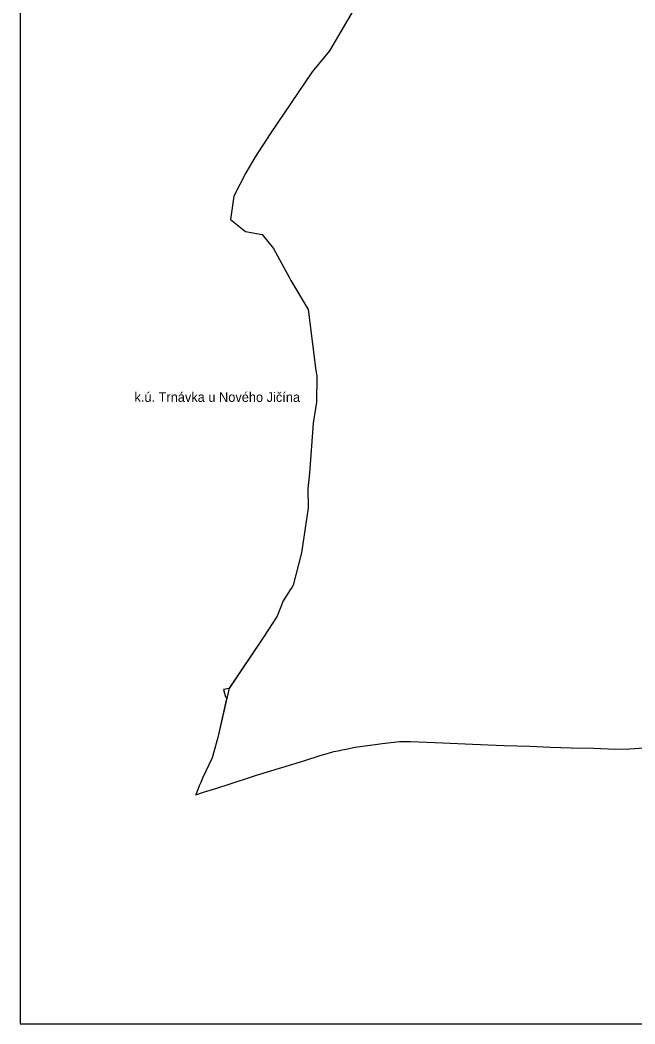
# Model space of a CAD drawing. Extents: x -478440 to -472455, y -1118045 to -1113755.
# Drawn here: x -478440 to -477154, y -1118000 to -1115899 of the extents above; entities that cross this region are included whole.
import ezdxf

# ---------------------------------------------------------------- set-up
doc = ezdxf.new("R2010")
doc.units = 0
for name, color, linetype in [('hranice kú', 7, 'Continuous'), ('Implicitní', 7, 'Continuous'), ('ObPÚ', 7, 'Continuous'), ('okolní k_ú_', 7, 'Continuous')]:
    doc.layers.add(name, color=color, linetype=linetype)

msp = doc.modelspace()

# ---------------------------------------------------------------- linework, layer by layer
at = {"layer": 'hranice kú'}
for p, q in [((-477745.7, -1115882.6), (-477792.7, -1115963.5)), ((-477792.7, -1115963.5), (-477829.2, -1116007.1)), ((-477829.2, -1116007.1), (-477917, -1116137.1)), ((-477917, -1116137.1), (-477949.4, -1116186.8)), ((-477949.4, -1116186.8), (-477967.8, -1116218.8)), ((-477967.8, -1116218.8), (-477992.9, -1116267.5)), ((-477992.9, -1116267.5), (-478000.3, -1116316.6)), ((-478000.3, -1116316.6), (-477968.7, -1116341.6)), ((-477968.7, -1116341.6), (-477933.8, -1116347.4)), ((-477933.8, -1116347.4), (-477910, -1116376.7)), ((-477910, -1116376.7), (-477876.7, -1116438.2)), ((-477876.7, -1116438.2), (-477873.6, -1116444)), ((-477873.6, -1116444), (-477837.5, -1116504.5)), ((-477837.5, -1116504.5), (-477821.5, -1116632.6)), ((-477821.5, -1116632.6), (-477819.1, -1116643.3)), ((-477819.1, -1116643.3), (-477819.9, -1116698.8)), ((-477819.9, -1116698.8), (-477826.9, -1116742.9)), ((-477826.9, -1116742.9), (-477835, -1116847.4)), ((-477835, -1116847.4), (-477838.2, -1116880.3)), ((-477838.2, -1116880.3), (-477837.4, -1116919.6)), ((-477837.4, -1116919.6), (-477851.4, -1117014.1)), ((-477851.4, -1117014.1), (-477868.8, -1117081.8)), ((-477871.9, -1117086.5), (-477874.9, -1117091.3)), ((-477868.8, -1117081.8), (-477871.9, -1117086.5)), ((-477874.9, -1117091.3), (-477889.7, -1117114.6)), ((-477889.7, -1117114.6), (-477902.7, -1117146.6)), ((-477902.7, -1117146.6), (-477931, -1117190.8)), ((-477931, -1117190.8), (-478003, -1117297.4)), ((-478003, -1117297.4), (-478026.4, -1117400.7)), ((-478026.4, -1117400.7), (-478038.6, -1117443)), ((-477766.4, -1117426.5), (-477761.5, -1117425.5)), ((-477761.5, -1117425.5), (-477739.4, -1117421.1)), ((-477739.4, -1117421.1), (-477692.8, -1117414.3)), ((-477692.8, -1117414.3), (-477683, -1117413.2)), ((-477683, -1117413.2), (-477646.5, -1117409)), ((-477646.5, -1117409), (-477622.5, -1117408.8)), ((-477622.5, -1117408.8), (-477556, -1117411.8)), ((-477556, -1117411.8), (-477494.1, -1117414.8)), ((-477494.1, -1117414.8), (-477427.6, -1117417.5)), ((-477427.6, -1117417.5), (-477374.1, -1117418.9)), ((-477374.1, -1117418.9), (-477330.4, -1117420.6)), ((-477330.4, -1117420.6), (-477287.5, -1117422.1)), ((-477287.5, -1117422.1), (-477240.8, -1117423)), ((-477240.8, -1117423), (-477193.8, -1117425.2)), ((-477193.8, -1117425.2), (-477165.8, -1117424.6)), ((-477165.8, -1117424.6), (-477134.7, -1117422.1)), ((-478038.6, -1117443), (-478058.5, -1117486)), ((-477846.5, -1117449.7), (-477810.1, -1117437.4)), ((-477810.1, -1117437.4), (-477802.8, -1117435.4)), ((-477802.8, -1117435.4), (-477797.7, -1117434)), ((-477797.7, -1117434), (-477792.8, -1117432.8)), ((-477792.8, -1117432.8), (-477783.8, -1117430)), ((-477783.8, -1117430), (-477771.4, -1117427.5)), ((-477771.4, -1117427.5), (-477766.4, -1117426.5)), ((-477945.6, -1117479.7), (-477846.5, -1117449.7)), ((-478058.5, -1117486), (-478062.4, -1117495)), ((-478009.3, -1117500.1), (-477945.6, -1117479.7)), ((-478065.9, -1117501.8), (-478072.8, -1117520.4)), ((-478062.4, -1117495), (-478065.9, -1117501.8)), ((-478049.8, -1117513.1), (-478028.9, -1117506.3)), ((-478028.9, -1117506.3), (-478024.4, -1117504.9)), ((-478024.4, -1117504.9), (-478019.9, -1117503.5)), ((-478019.9, -1117503.5), (-478009.3, -1117500.1)), ((-478072.8, -1117520.4), (-478058.8, -1117515.9)), ((-478058.8, -1117515.9), (-478054.3, -1117514.5)), ((-478054.3, -1117514.5), (-478049.8, -1117513.1))]:
    msp.add_line(p, q, dxfattribs=at)
at = {"layer": 'Implicitní'}
msp.add_lwpolyline([(-478440.1, -1118000.1), (-472500.1, -1118000.1), (-472500.1, -1113800.1), (-478440.1, -1113800.1)], close=True, dxfattribs=at)
at = {"layer": 'ObPÚ'}
for p, q in [((-477745.7, -1115882.6), (-477792.7, -1115963.5)), ((-477792.7, -1115963.5), (-477829.2, -1116007.1)), ((-477829.2, -1116007.1), (-477917, -1116137.1)), ((-477917, -1116137.1), (-477949.4, -1116186.8)), ((-477949.4, -1116186.8), (-477967.8, -1116218.8)), ((-477967.8, -1116218.8), (-477992.9, -1116267.5)), ((-477992.9, -1116267.5), (-478000.3, -1116316.6)), ((-478000.3, -1116316.6), (-477968.7, -1116341.6)), ((-477968.7, -1116341.6), (-477933.8, -1116347.4)), ((-477933.8, -1116347.4), (-477910, -1116376.7)), ((-477910, -1116376.7), (-477876.7, -1116438.2)), ((-477876.7, -1116438.2), (-477873.6, -1116444)), ((-477873.6, -1116444), (-477837.5, -1116504.5)), ((-477837.5, -1116504.5), (-477821.5, -1116632.6)), ((-477821.5, -1116632.6), (-477819.1, -1116643.3)), ((-477819.1, -1116643.3), (-477819.9, -1116698.8)), ((-477819.9, -1116698.8), (-477826.9, -1116742.9)), ((-477826.9, -1116742.9), (-477835, -1116847.4)), ((-477835, -1116847.4), (-477838.2, -1116880.3)), ((-477838.2, -1116880.3), (-477837.4, -1116919.6)), ((-477837.4, -1116919.6), (-477851.4, -1117014.1)), ((-477851.4, -1117014.1), (-477868.8, -1117081.8)), ((-477871.9, -1117086.5), (-477874.9, -1117091.3)), ((-477868.8, -1117081.8), (-477871.9, -1117086.5)), ((-477874.9, -1117091.3), (-477889.7, -1117114.6)), ((-477889.7, -1117114.6), (-477902.7, -1117146.6)), ((-477902.7, -1117146.6), (-477931, -1117190.8)), ((-478007.7, -1117316.1), (-478026.4, -1117400.7)), ((-478026.4, -1117400.7), (-478038.6, -1117443)), ((-477766.4, -1117426.5), (-477761.5, -1117425.5)), ((-477761.5, -1117425.5), (-477739.4, -1117421.1)), ((-477739.4, -1117421.1), (-477692.8, -1117414.3)), ((-477692.8, -1117414.3), (-477683, -1117413.2)), ((-477683, -1117413.2), (-477646.5, -1117409)), ((-477646.5, -1117409), (-477622.5, -1117408.8)), ((-477622.5, -1117408.8), (-477556, -1117411.8)), ((-477556, -1117411.8), (-477494.1, -1117414.8)), ((-477494.1, -1117414.8), (-477427.6, -1117417.5)), ((-477427.6, -1117417.5), (-477374.1, -1117418.9)), ((-477374.1, -1117418.9), (-477330.4, -1117420.6)), ((-477330.4, -1117420.6), (-477287.5, -1117422.1)), ((-477287.5, -1117422.1), (-477240.8, -1117423)), ((-477240.8, -1117423), (-477193.8, -1117425.2)), ((-477193.8, -1117425.2), (-477165.8, -1117424.6)), ((-477165.8, -1117424.6), (-477134.7, -1117422.1)), ((-478038.6, -1117443), (-478058.5, -1117486)), ((-477846.5, -1117449.7), (-477810.1, -1117437.4)), ((-477810.1, -1117437.4), (-477802.8, -1117435.4)), ((-477802.8, -1117435.4), (-477797.7, -1117434)), ((-477797.7, -1117434), (-477792.8, -1117432.8)), ((-477792.8, -1117432.8), (-477783.8, -1117430)), ((-477783.8, -1117430), (-477771.4, -1117427.5)), ((-477771.4, -1117427.5), (-477766.4, -1117426.5)), ((-477945.6, -1117479.7), (-477846.5, -1117449.7)), ((-478058.5, -1117486), (-478062.4, -1117495)), ((-478009.3, -1117500.1), (-477945.6, -1117479.7)), ((-478065.9, -1117501.8), (-478072.8, -1117520.4)), ((-478062.4, -1117495), (-478065.9, -1117501.8)), ((-478049.8, -1117513.1), (-478028.9, -1117506.3)), ((-478028.9, -1117506.3), (-478024.4, -1117504.9)), ((-478024.4, -1117504.9), (-478019.9, -1117503.5)), ((-478019.9, -1117503.5), (-478009.3, -1117500.1)), ((-478072.8, -1117520.4), (-478058.8, -1117515.9)), ((-478058.8, -1117515.9), (-478054.3, -1117514.5)), ((-478054.3, -1117514.5), (-478049.8, -1117513.1))]:
    msp.add_line(p, q, dxfattribs=at)
msp.add_lwpolyline([(-477931, -1117190.8), (-478003.1, -1117297.8), (-478014.9, -1117299.8), (-478010.7, -1117315.5), (-478007.7, -1117316.1)], dxfattribs=at)

# ---------------------------------------------------------------- texts
at = {"layer": 'okolní k_ú_'}
msp.add_text('k.ú. Trnávka u Nového Jičína', height=20, rotation=359.9619, dxfattribs=at).set_placement((-478200.9, -1116697.9))

doc.saveas('drawing.dxf')
